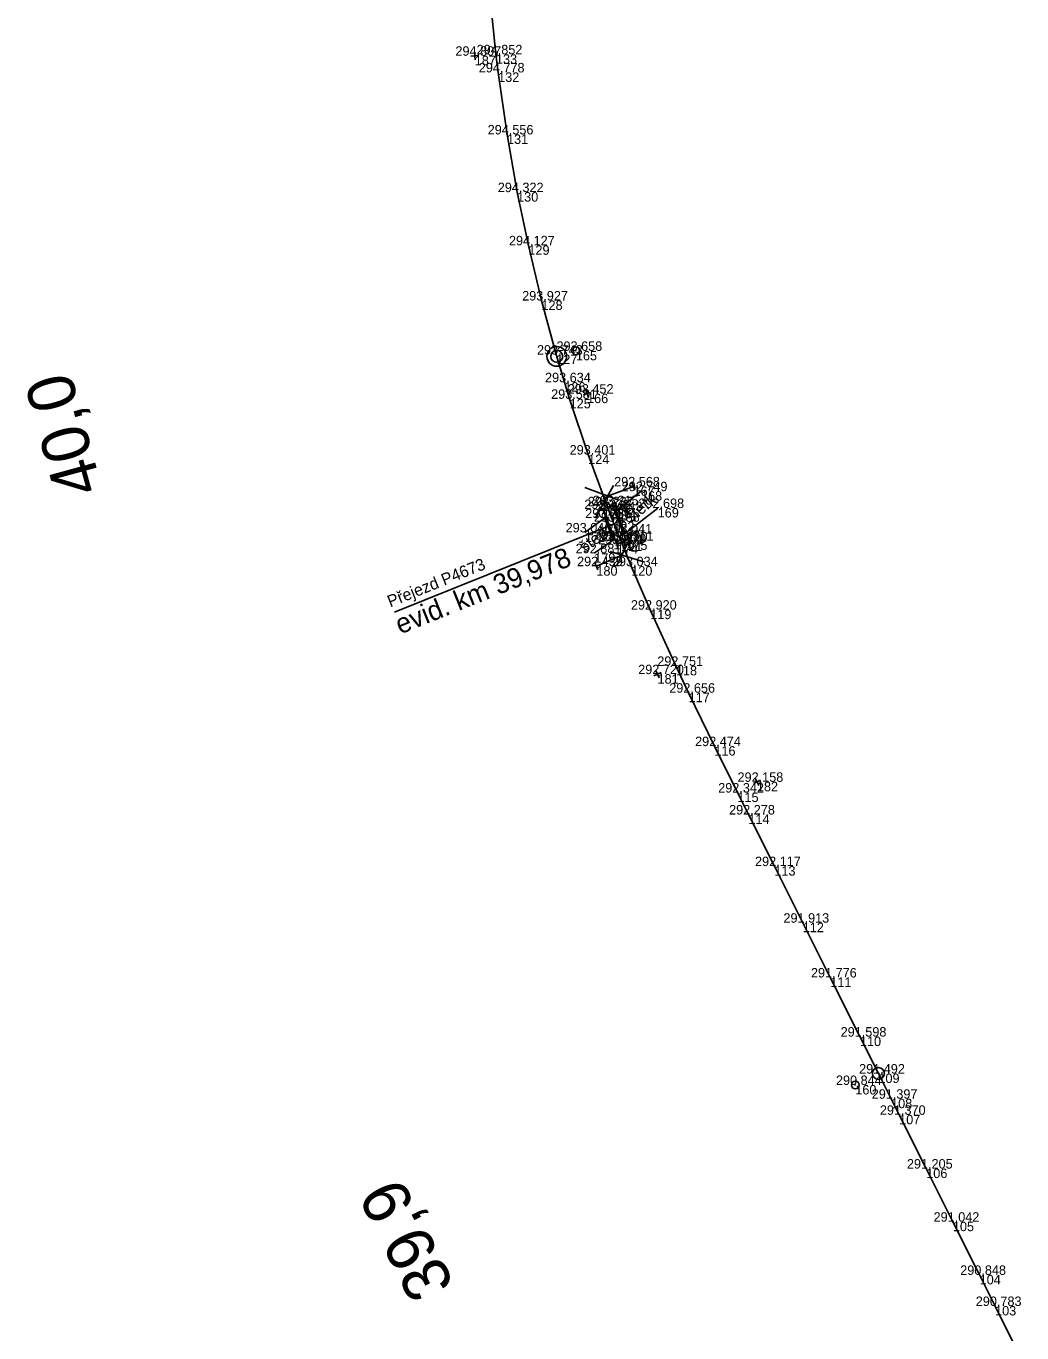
# Model space of a CAD drawing. Extents: x -684938 to -684389, y -1007777 to -1006471.
# Drawn here: x -684574.3 to -684448, y -1007456.7 to -1007291.1 of the extents above; entities that cross this region are included whole.
import ezdxf

# ---------------------------------------------------------------- set-up
doc = ezdxf.new("R2010")
doc.units = 0
for name, color, linetype in [('Vrstva 1', 7, 'Continuous'), ('Vrstva 4', 7, 'Continuous'), ('Vrstva 51', 7, 'Continuous'), ('Vrstva 60', 7, 'Continuous'), ('Vrstva 61', 7, 'Continuous'), ('Vrstva 7', 7, 'Continuous')]:
    doc.layers.add(name, color=color, linetype=linetype)

msp = doc.modelspace()

# ---------------------------------------------------------------- linework, layer by layer
at = {"layer": 'Vrstva 1'}
msp.add_lwpolyline([(-684448.04, -1007460.11), (-684451.43, -1007453.3), (-684453.39, -1007449.36), (-684456.78, -1007442.62), (-684460.16, -1007435.89), (-684463.59, -1007429.08), (-684464.61, -1007427.04), (-684466.22, -1007423.85), (-684468.56, -1007419.17), (-684472.32, -1007411.68), (-684475.81, -1007404.74), (-684479.41, -1007397.57), (-684482.7, -1007391.03), (-684484.09, -1007388.25), (-684487.01, -1007382.37), (-684490.28, -1007375.6), (-684491.89, -1007372.2), (-684495.14, -1007365.08), (-684497.55, -1007359.57), (-684498.83, -1007356.43), (-684499.83, -1007353.94), (-684500.59, -1007351.98), (-684503.01, -1007345.43), (-684505.36, -1007338.37), (-684506.03, -1007336.26), (-684507.05, -1007332.77), (-684508.93, -1007325.91), (-684510.59, -1007318.92), (-684512.02, -1007312.18), (-684513.3, -1007304.87), (-684514.42, -1007297.01), (-684514.7, -1007294.72), (-684515.43, -1007287.58)], dxfattribs=at)
at = {"layer": 'Vrstva 4'}
for p, q in [((-684497.09, -1007349.93), (-684497.43, -1007348.99)), ((-684499.12, -1007351.21), (-684503.44, -1007349.61)), ((-684502.06, -1007353.36), (-684499.81, -1007349.33)), ((-684497.26, -1007349.46), (-684500.56, -1007350.68)), ((-684527.56, -1007365.39), (-684499.72, -1007354.19)), ((-684497.41, -1007355.4), (-684499.41, -1007359.55)), ((-684502.17, -1007359.11), (-684501.77, -1007360.03)), ((-684501.97, -1007359.57), (-684498.75, -1007358.16)), ((-684500.21, -1007357.72), (-684495.81, -1007359.06))]:
    msp.add_line(p, q, dxfattribs=at)
msp.add_lwpolyline([(-684499.38, -1007356.8), (-684501.15, -1007352.33), (-684499.97, -1007351.84), (-684498.18, -1007356.32), (-684499.38, -1007356.8)], dxfattribs=at)
at = {"layer": 'Vrstva 51'}
for points in [[(-684496.31, -1007350.07), (-684499.49, -1007352.59), (-684498.34, -1007355.44), (-684494.2, -1007352.2)], [(-684503.42, -1007355.29), (-684500.94, -1007353.48), (-684499.82, -1007356.22), (-684502.24, -1007357.93)]]:
    msp.add_lwpolyline(points, dxfattribs=at)
at = {"layer": 'Vrstva 60'}
for p, q in [((-684517.39, -1007294.9), (-684517.39, -1007294.9)), ((-684514.7, -1007294.72), (-684514.7, -1007294.72)), ((-684514.42, -1007297.01), (-684514.42, -1007297.01)), ((-684513.3, -1007304.87), (-684513.3, -1007304.87)), ((-684512.02, -1007312.18), (-684512.02, -1007312.18)), ((-684510.59, -1007318.92), (-684510.59, -1007318.92)), ((-684508.93, -1007325.91), (-684508.93, -1007325.91)), ((-684504.57, -1007332.29), (-684504.57, -1007332.29)), ((-684507.05, -1007332.77), (-684507.05, -1007332.77)), ((-684506.03, -1007336.26), (-684506.03, -1007336.26)), ((-684505.36, -1007338.37), (-684505.36, -1007338.37)), ((-684503.15, -1007337.71), (-684503.15, -1007337.71)), ((-684503.01, -1007345.43), (-684503.01, -1007345.43)), ((-684497.26, -1007349.46), (-684497.26, -1007349.46)), ((-684496.31, -1007350.07), (-684496.31, -1007350.07)), ((-684501.15, -1007352.33), (-684501.15, -1007352.33)), ((-684500.59, -1007351.98), (-684500.59, -1007351.98)), ((-684499.97, -1007351.84), (-684499.97, -1007351.84)), ((-684494.2, -1007352.2), (-684494.2, -1007352.2)), ((-684500.94, -1007353.48), (-684500.94, -1007353.48)), ((-684499.83, -1007353.94), (-684499.83, -1007353.94)), ((-684499.49, -1007352.59), (-684499.49, -1007352.59)), ((-684503.42, -1007355.29), (-684503.42, -1007355.29)), ((-684498.34, -1007355.44), (-684498.34, -1007355.44)), ((-684499.82, -1007356.22), (-684499.82, -1007356.22)), ((-684499.38, -1007356.8), (-684499.38, -1007356.8)), ((-684498.83, -1007356.43), (-684498.83, -1007356.43)), ((-684498.18, -1007356.32), (-684498.18, -1007356.32)), ((-684502.24, -1007357.93), (-684502.24, -1007357.93)), ((-684501.97, -1007359.57), (-684501.97, -1007359.57)), ((-684497.55, -1007359.57), (-684497.55, -1007359.57)), ((-684495.14, -1007365.08), (-684495.14, -1007365.08)), ((-684491.89, -1007372.2), (-684491.89, -1007372.2)), ((-684494.22, -1007373.25), (-684494.22, -1007373.25)), ((-684490.28, -1007375.6), (-684490.28, -1007375.6)), ((-684487.01, -1007382.37), (-684487.01, -1007382.37)), ((-684481.62, -1007386.89), (-684481.62, -1007386.89)), ((-684484.09, -1007388.25), (-684484.09, -1007388.25)), ((-684482.7, -1007391.03), (-684482.7, -1007391.03)), ((-684479.41, -1007397.57), (-684479.41, -1007397.57)), ((-684475.81, -1007404.74), (-684475.81, -1007404.74)), ((-684472.32, -1007411.68), (-684472.32, -1007411.68)), ((-684468.56, -1007419.17), (-684468.56, -1007419.17)), ((-684469.15, -1007425.3), (-684469.15, -1007425.3)), ((-684466.22, -1007423.85), (-684466.22, -1007423.85)), ((-684464.61, -1007427.04), (-684464.61, -1007427.04)), ((-684463.59, -1007429.08), (-684463.59, -1007429.08)), ((-684460.16, -1007435.89), (-684460.16, -1007435.89)), ((-684456.78, -1007442.62), (-684456.78, -1007442.62)), ((-684453.39, -1007449.36), (-684453.39, -1007449.36)), ((-684451.43, -1007453.3), (-684451.43, -1007453.3))]:
    msp.add_line(p, q, dxfattribs=at)
at = {"layer": 'Vrstva 7'}
for p, q in [((-684517.34, -1007295.4), (-684517.44, -1007294.4)), ((-684517.89, -1007294.95), (-684516.89, -1007294.85)), ((-684504.56, -1007332.33), (-684504.59, -1007332.24)), ((-684503.62, -1007337.86), (-684502.68, -1007337.55)), ((-684502.99, -1007338.18), (-684503.31, -1007337.23)), ((-684494.68, -1007373.46), (-684493.77, -1007373.04)), ((-684494.02, -1007373.71), (-684494.43, -1007372.8)), ((-684482.07, -1007387.11), (-684481.17, -1007386.67)), ((-684481.4, -1007387.34), (-684481.84, -1007386.44)), ((-684469.12, -1007425.35), (-684469.17, -1007425.26))]:
    msp.add_line(p, q, dxfattribs=at)
for centre, radius in [((-684506.99, -1007332.99), 1.25), ((-684506.99, -1007332.99), 0.752), ((-684504.57, -1007332.29), 0.5), ((-684466.22, -1007423.84), 0.75), ((-684469.15, -1007425.3), 0.5)]:
    msp.add_circle(centre, radius, dxfattribs=at)

# ---------------------------------------------------------------- texts
at = {"layer": 'Vrstva 4'}
for s, height, p in [('evid. km 39,978', 2.5, (-684526.84, -1007368.23)), ('Přejezd P4673', 1.5, (-684528.1, -1007364.8))]:
    msp.add_text(s, height=height, rotation=21.9162, dxfattribs=at).set_placement(p)
at = {"layer": 'Vrstva 51'}
for rotation, p in [(38.0422, (-684497.61, -1007354.14)), (36.0082, (-684503.44, -1007357.91))]:
    msp.add_text('štěrk', height=1.5, rotation=rotation, dxfattribs=at).set_placement(p)
at = {"layer": 'Vrstva 60'}
for s, p in [('187', (-684517.39, -1007296.1)), ('133', (-684514.7, -1007295.92)), ('132', (-684514.42, -1007298.21)), ('131', (-684513.3, -1007306.07)), ('130', (-684512.02, -1007313.38)), ('129', (-684510.59, -1007320.12)), ('128', (-684508.93, -1007327.11)), ('165', (-684504.57, -1007333.49)), ('127', (-684507.05, -1007333.97)), ('126', (-684506.03, -1007337.46)), ('125', (-684505.36, -1007339.57)), ('166', (-684503.15, -1007338.91)), ('124', (-684503.01, -1007346.63)), ('167', (-684497.26, -1007350.66)), ('168', (-684496.31, -1007351.27)), ('173', (-684501.15, -1007353.53)), ('123', (-684500.59, -1007353.18)), ('172', (-684499.97, -1007353.04)), ('169', (-684494.2, -1007353.4)), ('177', (-684500.94, -1007354.69)), ('122', (-684499.83, -1007355.14)), ('171', (-684499.49, -1007353.79)), ('178', (-684503.42, -1007356.49)), ('170', (-684498.34, -1007356.64)), ('176', (-684499.82, -1007357.42)), ('174', (-684499.38, -1007358)), ('121', (-684498.83, -1007357.63)), ('175', (-684498.18, -1007357.52)), ('179', (-684502.24, -1007359.13)), ('180', (-684501.97, -1007360.77)), ('120', (-684497.55, -1007360.77)), ('119', (-684495.14, -1007366.28)), ('118', (-684491.89, -1007373.4)), ('181', (-684494.22, -1007374.45)), ('117', (-684490.28, -1007376.8)), ('116', (-684487.01, -1007383.57)), ('182', (-684481.62, -1007388.09)), ('115', (-684484.09, -1007389.45)), ('114', (-684482.7, -1007392.22)), ('113', (-684479.41, -1007398.77)), ('112', (-684475.81, -1007405.94)), ('111', (-684472.32, -1007412.88)), ('110', (-684468.56, -1007420.37)), ('160', (-684469.15, -1007426.5)), ('109', (-684466.22, -1007425.05)), ('108', (-684464.61, -1007428.24)), ('107', (-684463.59, -1007430.28)), ('106', (-684460.16, -1007437.09)), ('105', (-684456.78, -1007443.82)), ('104', (-684453.39, -1007450.56)), ('103', (-684451.43, -1007454.5))]:
    msp.add_text(s, height=1.2, dxfattribs=at).set_placement(p)
at = {"layer": 'Vrstva 61'}
for s, p in [('294.807', (-684519.84, -1007294.9)), ('294.852', (-684517.15, -1007294.72)), ('294.778', (-684516.88, -1007297.01)), ('294.556', (-684515.75, -1007304.87)), ('294.322', (-684514.47, -1007312.18)), ('294.127', (-684513.05, -1007318.92)), ('293.927', (-684511.38, -1007325.91)), ('293.743', (-684509.5, -1007332.77)), ('293.658', (-684507.03, -1007332.29)), ('293.634', (-684508.48, -1007336.26)), ('293.581', (-684507.71, -1007338.37)), ('293.452', (-684505.6, -1007337.71)), ('293.401', (-684505.36, -1007345.43)), ('292.568', (-684499.72, -1007349.46)), ('292.749', (-684498.76, -1007350.07)), ('293.237', (-684503.05, -1007351.98)), ('293.215', (-684502.43, -1007351.84)), ('293.331', (-684503.5, -1007352.33)), ('293.256', (-684503.39, -1007353.48)), ('293.143', (-684501.94, -1007352.59)), ('292.698', (-684496.65, -1007352.2)), ('293.046', (-684505.87, -1007355.29)), ('293.188', (-684502.28, -1007353.94)), ('293.183', (-684502.27, -1007356.22)), ('293.201', (-684501.74, -1007356.8)), ('293.120', (-684501.28, -1007356.43)), ('293.041', (-684500.7, -1007355.44)), ('293.111', (-684500.53, -1007356.32)), ('292.881', (-684504.6, -1007357.93)), ('292.439', (-684504.42, -1007359.57)), ('293.034', (-684500, -1007359.57)), ('292.920', (-684497.59, -1007365.08)), ('292.720', (-684496.67, -1007373.25)), ('292.751', (-684494.25, -1007372.2)), ('292.656', (-684492.73, -1007375.6)), ('292.474', (-684489.46, -1007382.37)), ('292.342', (-684486.53, -1007388.25)), ('292.158', (-684484.08, -1007386.89)), ('292.278', (-684485.15, -1007391.03)), ('292.117', (-684481.86, -1007397.57)), ('291.913', (-684478.26, -1007404.74)), ('291.776', (-684474.77, -1007411.68)), ('291.598', (-684471.01, -1007419.17)), ('291.492', (-684468.67, -1007423.85)), ('290.844', (-684471.6, -1007425.3)), ('291.397', (-684467.07, -1007427.04)), ('291.370', (-684466.04, -1007429.08)), ('291.205', (-684462.61, -1007435.89)), ('291.042', (-684459.23, -1007442.62)), ('290.848', (-684455.85, -1007449.36)), ('290.783', (-684453.88, -1007453.3))]:
    msp.add_text(s, height=1.2, dxfattribs=at).set_placement(p)
at = {"layer": 'Vrstva 7'}
for s, rotation, p in [('40,0', 105.2883, (-684564.59, -1007349.77)), ('39,9', 116.5552, (-684519.89, -1007450.66))]:
    msp.add_text(s, height=6, rotation=rotation, dxfattribs=at).set_placement(p)

doc.saveas('drawing.dxf')
